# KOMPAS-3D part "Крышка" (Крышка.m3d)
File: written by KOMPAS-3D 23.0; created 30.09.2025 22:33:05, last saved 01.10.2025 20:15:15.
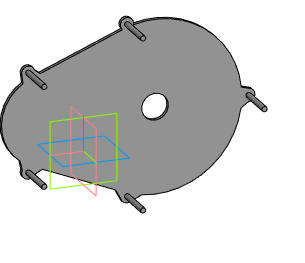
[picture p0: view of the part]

Document properties: Автор: Inspektor_Kot; Полное имя файла: I:\Autodesk Inventor Projects\ИМ-ИТ ЦД\Вариант 11\Крышка.m3d

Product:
- Part/product: Крышка
    Масса: 0.423039

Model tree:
1. Эскиз:2  (with: Элемент выдавливания:4, Элемент выдавливания:5)
2. Элемент выдавливания:1
     Расстояние 1 = 3
3. Эскиз:3  (with: Элемент выдавливания:1)
4. Элемент выдавливания:2
     Расстояние 1 = -35
5. Эскиз:4  (with: Элемент выдавливания:1, Элемент выдавливания:2)  (labels: Цилиндрическое зубчатое зацепление1\Шестерёнка большая)
6. Элемент выдавливания:4
     Расстояние 2 = 10

Referenced files in I:\Autodesk Inventor Projects\ИМ-ИТ ЦД\Вариант 11\: Мотор-редуктор.a3d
